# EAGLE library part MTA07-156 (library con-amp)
AMP connector
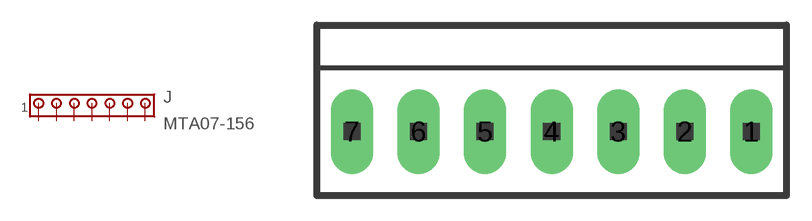
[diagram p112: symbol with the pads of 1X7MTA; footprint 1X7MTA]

Designator prefix J

## MTA07-156 (OC_FARNELL: unknown; OC_NEWARK: unknown)  [1X7MTA]
1  1  pas
2  2  pas
3  3  pas
4  4  pas
5  5  pas
6  6  pas
7  7  pas

## Footprint 1X7MTA (pad centres in mm)
AMP MTA connector
drill 1.676 long: 1 11.887,0; 2 7.925,0; 3 3.962,0; 4 0,0; 5 -3.962,0; 6 -7.925,0; 7 -11.887,0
